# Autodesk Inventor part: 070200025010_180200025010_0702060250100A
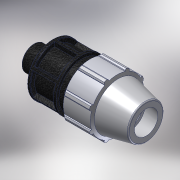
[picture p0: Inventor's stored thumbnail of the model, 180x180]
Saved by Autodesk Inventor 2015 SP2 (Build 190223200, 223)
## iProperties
Created: 2017-02
Part Number: 070200025010_180200025010_0702060250100A
Material: PVC-Piping
Description: PLASSON MALE ADAPTOR 25-1"
Document SubType Name: Modeling
Designer: KIM
Mass: 92.6774 g
Surface Area: 199.44 cm^2
Volume: 66.1981 cm^3
Density: 1.4 g/cm^3
Appearance: PTFE
Author: KIM
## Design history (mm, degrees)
derived "07020.ipt"
feature "Solid1::07020.ipt"
tag "TaggingFeature1"
body "Solid1"
other parameters: "d2" = 25, "d4" = 13.85714, "d5" = 24.25, "d7" = 54, "d8" = 40.5, "d9" = 13.85714, "d11" = 2.77143, "d12" = 43.2, "d13" = 120 deg, "d14" = 37.5, "d15" = 12 deg, "d16" = 48.6, "d18" = 1.25, "d19" = 35 deg, "d20" = 17.5 deg, "d21" = 50.22, "d23" = 0, "d25" = 360 deg, "d27" = 1.08, "d34" = 2.7, "d36" = 0, "d42" = 24.25, "d43" = 1.62, "d46" = 0.75, "d49" = 72, "d51" = 97, "d53" = 0.5, "d55" = 360 deg, "d57" = 33.249, "d58" = 19.9494, "d59" = 19.4, "d_" = 25, "E_" = 54, "H_" = 97, "l_" = 72, "R_" = 33.249
